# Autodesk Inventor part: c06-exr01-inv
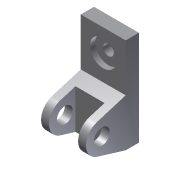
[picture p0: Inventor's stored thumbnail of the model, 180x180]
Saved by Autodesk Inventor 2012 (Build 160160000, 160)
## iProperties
Shininess: 77.0
Length Units: 11269
Angle Units: 11279
Time Units: 11290
Mass Units: 11283
Length Display Precision: 3
Angle Display Precision: 2
Created: 2001-12
Part Number: c06-exr01-inv
Document SubType Name: Modeling
Designer: Renu Muthoo
Density: 1 g/cm^3
Material: Default
Density: 0.0
Volumn: 0.0
Area: 0.0
PropertySet Name: Model Information
Control State: 0
Master: False
Checked Out: False
Author: Renu Muthoo
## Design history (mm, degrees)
node "Sketch1"
sketch "Sketch2"
  geometry: L1 (-8.12, 12.649)-(-8.12, 102.649); L2 (-8.12, 102.649)-(16.88, 102.649); L3 (16.88, 102.649)-(16.88, -77.351); L4 (16.88, -77.351)-(-8.12, -77.351); L5 (-8.12, -77.351)-(-61.829, -61.06); L6 (-61.829, -3.643)-(-8.12, 12.649); C1 r 15 at (-53.12, -32.351); A1 r 30 centre (-53.12, -32.351) between (-61.829, -3.643) and (-61.829, -61.06)
  constraints: 12 end point, 2 centre point, 2 equal length, 2 parallel, 2 point on circle, 2 tangent, 1 coincident, 1 perpendicular, 1 vertical
  dimensions: "d0" = 180 distance of L2.end L3.end; "d1" = 25 distance of L3.end L4.end; "d2" = 70 distance from line of L3 A1.centre; "d3" = 30 radius of A1; "d4" = 45 distance from line of L4 A1.centre; "d5" = 30 diameter of C1
extrude "Extrusion1" new body sketch "Sketch2" stored distance "d6" = 85; taper "d7" = 0 deg
sketch "Sketch3"
  geometry: L1 (-95, 20)-(-33.12, 20); L2 (-33.12, 20)-(-33.12, -81); L3 (-33.12, -81)-(-95, -81); L4 (-95, -81)-(-95, 20); C1 r 15 at (-53.12, -32.351) reference
  constraints: 8 end point, 2 parallel, 1 horizontal, 1 perpendicular
  dimensions: "d8" = 20 distance from line of C1.centre L2
extrude "Extrusion2" cut sketch "Sketch3" stored distance "d9" = 55; taper "d10" = 0 deg
sketch "Sketch4"
  geometry: L1 (85, -90)-(85, 0) reference; L2 (85, 0)-(0, 0) reference; 1 further point
  dimensions: "d11" = 42 distance from line of L2 point (42.5, -42); "d12" = 42.5 distance from line of L1 point (42.5, -42)
hole "Hole1" sketch "Sketch4" at (42.5, -42) diameter "d13" = 20; stored, may be unused: countersink angle "d17" = 82 deg, drill point angle "d19" = 118 deg; dims "d14" = 6, "d15" = 50, "d16" = 10, "d18" = 8
body "Solid1"
